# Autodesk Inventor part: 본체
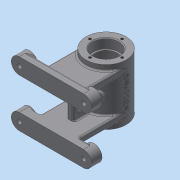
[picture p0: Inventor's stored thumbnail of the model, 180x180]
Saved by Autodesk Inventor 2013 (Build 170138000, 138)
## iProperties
Created: 2015-11
Part Number: 본체
Material: 일반
Document SubType Name: Modeling
Designer: Administrator
Density: 1 g/cm^3
Author: Administrator
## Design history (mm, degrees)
sketch "스케치1"
  geometry: C1 r 25 at (0, 0); 1 further point
  constraints: 1 centre point, 1 coincident
  dimensions: "d0" = 50 diameter of C1
extrude "돌출1" new body sketch "스케치1" stored distance "d1" = 70; taper "d2" = 0 deg
node "작업 평면1"
sketch "스케치2" dims "d4" = 20
  geometry: L1 (40, 20)-(-40, 20); L2 (-40, 20)-(-40, 40); L3 (-40, 40)-(40, 40); L4 (40, 40)-(40, 20); C1 r 10 at (40, 30); 4 further points
  constraints: 8 end point, 4 vertical alignment, 2 midpoint, 2 parallel, 1 centre point, 1 coincident, 1 horizontal, 1 perpendicular, 2 other
  dimensions: "d6" = 20 diameter of C1; "d7" = 20 distance of L1.end L2.end; "d8" = 80 distance between parallel lines of L2 L4; "d9" = 40 distance from line of L3 point (0, 0)
extrude "돌출2" join sketch "스케치2" distance "d10" = 10; taper "d11" = 0 deg
extrude "돌출3" join sketch "스케치2" distance "d12" = 13; taper "d13" = 0 deg
hole "구멍1" diameter "d16" = 6; stored, may be unused: countersink angle "d20" = 90 deg, drill point angle "d22" = 0 deg; dims "d14" = 10, "d15" = 10, "d17" = 6, "d18" = 12, "d19" = 4, "d21" = 8
hole "구멍2" diameter "d25" = 6; stored, may be unused: countersink angle "d29" = 90 deg, drill point angle "d31" = 0 deg; dims "d23" = 10, "d24" = 10, "d26" = 6, "d27" = 12, "d28" = 4, "d30" = 8
sketch "스케치3"
  geometry: L1 (0, 10)-(80, 10) reference; L2 (15, 68)-(15, 10); L3 (65, 68)-(65, 10); L4 (80, 0)-(80, 10) reference; L5 (80, 10)-(80, 13) reference; L6 (80, 0)-(0, 0) reference; L7 (0, 0)-(0, 10) reference; L8 (0, 10)-(80, 10) reference; L9 (0, 10)-(0, 13) reference; L10 (80, 0)-(80, 10) reference; L11 (80, 10)-(80, 13) reference; L12 (80, 0)-(0, 0) reference; L13 (0, 0)-(0, 10) reference; L14 (0, 10)-(80, 10) reference; L15 (0, 10)-(0, 13) reference; L16 (15, 10)-(65, 10); C1 r 25 at (40, 68) reference; C2 r 25 at (40, 68) reference; A1 r 25 centre (40, 68) between (15, 68) and (65, 68); 1 further point
  constraints: 6 end point, 3 perpendicular, 2 point on circle, 2 point on line, 2 tangent, 1 centre point, 1 coincident
extrude "돌출4" join sketch "스케치3" distance "d32" = 8; taper "d33" = 0 deg
sketch "스케치4"
  geometry: C1 r 25 at (0, 0) reference; C2 r 21 at (0, 0); 1 further point
  constraints: 1 centre point, 1 coincident
  dimensions: "d34" = 42 diameter of C2
extrude "돌출5" cut sketch "스케치4" stored distance "d35" = 42; taper "d36" = 0 deg
hole "구멍3" diameter "d39" = 28; stored, may be unused: countersink angle "d43" = 90 deg, drill point angle "d45" = 0 deg; dims "d40" = 6, "d41" = 32, "d42" = 12, "d44" = 14, "d46" = 10, "d47" = 10
hole "구멍4" diameter "d50" = 28; stored, may be unused: countersink angle "d54" = 90 deg, drill point angle "d56" = 0 deg; dims "d48" = 10, "d49" = 10, "d51" = 6, "d52" = 32, "d53" = 12, "d55" = 14
sketch "스케치5"
  geometry: L1 (25, 35)-(25, -35) reference; L2 (25, -35)-(16, -35) reference; L3 (16, -35)-(16, -23) reference; L4 (16, -23)-(14, -23) reference; L5 (14, -23)-(14, -21) reference; L6 (14, -21)-(21, -21) reference; L7 (21, -21)-(21, 21) reference; L8 (21, 21)-(14, 21) reference; L9 (14, 21)-(14, 23) reference; L10 (14, 23)-(16, 23) reference; L11 (16, 23)-(16, 35) reference; L12 (16, 35)-(25, 35) reference; L13 (-68, 20)-(-68, 40) reference; L14 (-68, 40)-(-58, 40) reference; L15 (-58, 40)-(-58, 28) reference; L16 (-58, 28)-(-25, 28) reference; L17 (-25, 28)-(-25, 35) reference; L18 (-25, 35)-(-16, 35) reference; L19 (-16, 35)-(-16, 23) reference; L20 (-16, 23)-(-14, 23) reference; L21 (-14, 23)-(-14, 21) reference; L22 (-14, 21)-(-21, 21) reference; L23 (-21, 21)-(-21, -21) reference; L24 (-21, -21)-(-14, -21) reference; L25 (-14, -21)-(-14, -23) reference; L26 (-14, -23)-(-16, -23) reference; L27 (-16, -23)-(-16, -35) reference; L28 (-16, -35)-(-25, -35) reference; L29 (-25, -35)-(-25, -28) reference; L30 (-25, -28)-(-58, -28) reference; L31 (-58, -28)-(-58, -40) reference; L32 (-58, -40)-(-68, -40) reference; L33 (-68, -40)-(-68, -20) reference; L34 (-68, -20)-(-25, -20) reference; L35 (-25, -20)-(-25, 20) reference; L36 (-25, 20)-(-68, 20) reference; L37 (-45, 20)-(-45, -20); 1 further point
  constraints: 2 end point, 2 point on line, 1 perpendicular
  dimensions: "d57" = 20 distance between parallel lines of L35 L37
feature "리브1" sketch "스케치5" dims "d58" = 1, "d59" = 8, "d60" = 0, "d61" = 0, "d62" = 1, "d63" = 1
sketch "스케치6"
  geometry: L1 (0, 0)-(-40, 0) reference; L2 (-28, 13.5)-(-12, 13.5); L3 (-12, 6.5)-(-28, 6.5); L4 (13, -23)-(7, -23) reference; A1 r 3.5 centre (-12, 10) between (-12, 6.5) and (-12, 13.5); A2 r 3.5 centre (-28, 10) between (-28, 13.5) and (-28, 6.5); 3 further points
  constraints: 4 end point, 4 point on circle, 4 tangent, 2 centre point, 2 midpoint, 2 parallel, 1 vertical alignment
  dimensions: "d64" = 3.5 radius of A1; "d66" = 33 distance from line of A1.centre L4; "d67" = 16 distance of A1.centre A2.centre
extrude "돌출6" cut sketch "스케치6" stored distance "d68" = 8; taper "d69" = 0 deg
sketch "스케치7"
  geometry: C1 r 25 at (0, 0) reference; 1 further point
  constraints: 1 vertical alignment
  dimensions: "d70" = 20 distance of point (0, 20) C1.centre
hole "구멍5" sketch "스케치7" at (0, 20) diameter "d71" = 3.242; stored, may be unused: countersink angle "d75" = 90 deg, drill point angle "d77" = 118 deg; dims "d72" = 8, "d73" = 32, "d74" = 12, "d76" = 10
node "작업 평면2"
sketch "스케치8"
  geometry: C1 r 5 at (0, 0); 1 further point
  constraints: 1 centre point, 1 coincident
  dimensions: "d82" = 10 diameter of C1
extrude "돌출7" join sketch "스케치8" stored distance "d84" = 3; taper "d85" = 0 deg
hole "구멍6" diameter "d88" = 5.188; stored, may be unused: countersink angle "d92" = 90 deg, drill point angle "d94" = 0 deg; dims "d86" = 10, "d87" = 10, "d89" = 8, "d90" = 32, "d91" = 12, "d93" = 10
sketch "스케치9"
  geometry: L1 (0, 0)-(23.693, -41.038); L2 (0, 0)-(0, -49.131); L3 (4, -45)-(-4, -45) reference; L4 (-4, -45)-(-4, -38.5) reference; L5 (-4, -38.5)-(4, -38.5) reference; L6 (4, -38.5)-(4, -45) reference; L7 (-5, 24.495)-(-5, 28) reference; L8 (-5, 28)-(-2.594, 28) reference; L9 (-2.594, 28)-(-2.594, 20.839) reference; L10 (2.594, 20.839)-(2.594, 28) reference; L11 (2.594, 28)-(5, 28) reference; L12 (5, 28)-(5, 24.495) reference; L13 (4, -24.678)-(4, -31.5) reference; L14 (4, -31.5)-(-4, -31.5) reference; L15 (-4, -31.5)-(-4, -24.678) reference; A1 r 21 centre (0, 0) between (-2.594, 20.839) and (2.594, 20.839) reference; A2 r 25 centre (0, 0) between (4, -24.678) and (5, 24.495) reference; A3 r 25 centre (0, 0) between (-5, 24.495) and (-4, -24.678) reference
  constraints: 4 end point, 1 vertical
  dimensions: "d95" = 30 deg angle of L2 L1
  node "절단 모서리 투영5"
node "작업 평면3"
node "작업 평면4"
sketch "스케치10"
  geometry: L1 (-16, 23)-(-14, 23) reference; L2 (-14, 23)-(-14, 21) reference; L3 (-14, 21)-(-21, 21) reference; L4 (-21, 21)-(-21, -21) reference; L5 (-21, -21)-(-14, -21) reference; L6 (-14, -21)-(-14, -23) reference; L7 (-14, -23)-(-16, -23) reference; L8 (-16, -23)-(-16, -35) reference; L9 (-16, -35)-(-25, -35) reference; L10 (-25, -35)-(-25, 35) reference; L11 (-25, 35)-(-16, 35) reference; L12 (-16, 35)-(-16, 23) reference; L13 (14, 23)-(16, 23) reference; L14 (16, 23)-(16, 35) reference; L15 (16, 35)-(25, 35) reference; L16 (25, 35)-(25, 28) reference; L17 (25, 28)-(50, 28) reference; L18 (50, 28)-(50, 20) reference; L19 (50, 20)-(25, 20) reference; L20 (25, 20)-(25, -20) reference; L21 (25, -20)-(50, -20) reference; L22 (50, -20)-(50, -28) reference; L23 (50, -28)-(25, -28) reference; L24 (25, -28)-(25, -35) reference; L25 (25, -35)-(16, -35) reference; L26 (16, -35)-(16, -23) reference; L27 (16, -23)-(14, -23) reference; L28 (14, -23)-(14, -21) reference; L29 (14, -21)-(21, -21) reference; L30 (21, -21)-(21, 21) reference; L31 (21, 21)-(14, 21) reference; L32 (14, 21)-(14, 23) reference; L33 (68.127, -30.872)-(68.127, -29.128) reference; L34 (78.52, -32.907)-(78.52, -40) reference; L35 (78.52, -40)-(66.973, -40) reference; L36 (66.973, -40)-(66.973, -37.588) reference; L37 (63.509, -35.658)-(63.509, -24.342) reference; L38 (66.973, -22.412)-(66.973, -20) reference; L39 (66.973, -20)-(78.52, -20) reference; L40 (78.52, -20)-(78.52, -27.093) reference; L41 (68.127, 29.128)-(68.127, 30.872) reference; L42 (78.52, 27.093)-(78.52, 20) reference; L43 (78.52, 20)-(66.973, 20) reference; L44 (66.973, 20)-(66.973, 22.412) reference; L45 (63.509, 24.342)-(63.509, 35.658) reference; L46 (66.973, 37.588)-(66.973, 40) reference; L47 (66.973, 40)-(78.52, 40) reference; L48 (78.52, 40)-(78.52, 32.907) reference; 9 further points; 8 other entities
  constraints: 8 other
  node "절단 모서리 투영6"
node "작업 평면5"
sketch "스케치11"
  geometry: 1 further point
node "작업 평면6"
sketch "스케치12"
  geometry: C1 r 6 at (0, -20); 1 further point
  constraints: 1 centre point, 1 coincident
  dimensions: "d98" = 12 diameter of C1
extrude "돌출8" join sketch "스케치12" stored distance "d99" = 8; taper "d100" = 0 deg
hole "구멍7" diameter "d103" = 5.188; stored, may be unused: countersink angle "d107" = 90 deg, drill point angle "d109" = 0 deg; dims "d101" = 10, "d102" = 10, "d104" = 8, "d105" = 32, "d106" = 12, "d108" = 10
fillet "모깎기1" dims "d110" = 2, "d111" = 3.5, "d112" = 0.3
chamfer "모따기1" distance "d113" = 1; stored, may be unused: second distance "d114" = 2, angle "d115" = 45 deg
fillet "모깎기2" dims "d116" = 2
fillet "모깎기3" dims "d117" = 2
fillet "모깎기5" dims "d119" = 3
node "작업 평면7"
sketch "스케치13"
  geometry: 2 further points
  constraints: 1 coincident, 1 other
feature "엠보싱1" sketch "스케치13" dims "d16" = 6, "d121" = 0.5, "d122" = 0
fillet "모깎기6" dims "d123" = 2
chamfer "모따기2" distance "d124" = 1; stored, may be unused: second distance "d125" = 2, angle "d126" = 45 deg
node "솔리드1"
mirror "대칭1"
pattern_circular "원형 패턴1" dims angle "d79" = 360 deg
mirror "대칭2"
mirror "대칭3"
node "절단 모서리 투영1"
node "절단 모서리 투영2"
node "절단 모서리 투영3"
node "절단 모서리 투영4"
other parameters: "d3" = -68, "d81" = 28, "d96" = 90 deg, "d97" = 3, "d120" = 25
